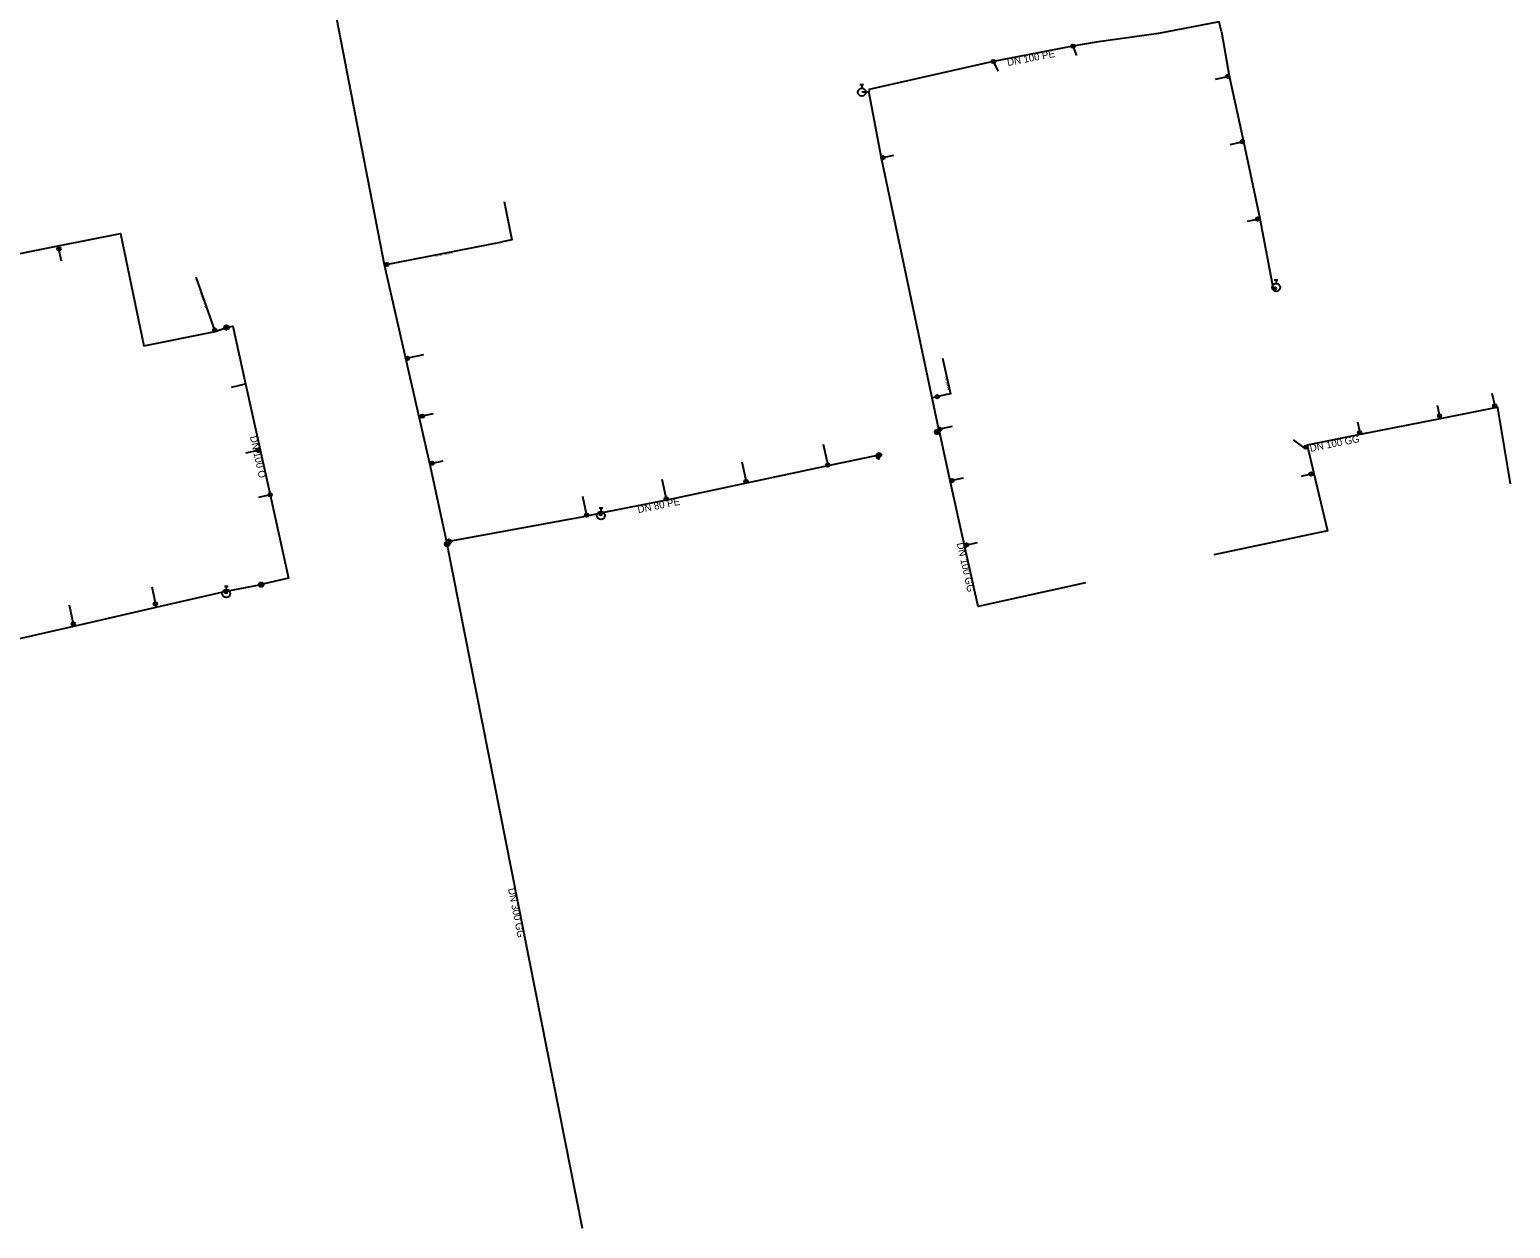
# Model space of a CAD drawing. Extents: x -452548 to -451108, y -1100145 to -1099658.
# Drawn here: x -452071.3 to -451742.6, y -1100145 to -1099878.8 of the extents above; entities that cross this region are included whole.
import ezdxf

# ---------------------------------------------------------------- set-up
doc = ezdxf.new("R2010")
doc.units = 0
for name, color, linetype in [('_hydrantova_odbocka_', 7, 'Continuous'), ('_kalosvod_', 7, 'Continuous'), ('_pripojka_prevzato_z_dokumentace_', 7, 'Continuous'), ('_pripojka_priblizne_', 7, 'Continuous'), ('_voda_smvak_prevzato_z_dokumentace_', 7, 'Continuous'), ('Default', 7, 'Continuous'), ('MoLevel 27', 7, 'Continuous'), ('MoLevel 28', 7, 'Continuous'), ('MoLevel 32', 7, 'Continuous'), ('MoLevel 46', 7, 'Continuous'), ('MoLevel 53', 7, 'Continuous'), ('MoLevel 55', 7, 'Continuous')]:
    doc.layers.add(name, color=color, linetype=linetype)

# ---------------------------------------------------------------- blocks, each defined once
blk = doc.blocks.new('_uzaver_')
at = {"layer": 'Default'}
for p, q in [((-0.000035, -0.000035), (0.000035, 0.000035)), ((0.000035, -0.000035), (-0.000035, 0.000035))]:
    blk.add_line(p, q, dxfattribs=at)
for radius in [0.00005, 0.0000025]:
    blk.add_circle((0, 0), radius, dxfattribs=at)
blk = doc.blocks.new('_uzaver_pripojka_')
at = {"layer": 'Default'}
for p, q in [((-0.000035, -0.000035), (0.000035, 0.000035)), ((0.000035, -0.000035), (-0.000035, 0.000035))]:
    blk.add_line(p, q, dxfattribs=at)
for radius in [0.00005, 0.0000025]:
    blk.add_circle((0, 0), radius, dxfattribs=at)
blk = doc.blocks.new('_hydrant_voda_')
at = {"layer": 'Default'}
for p, q in [((-0.000023, 0.000095), (0.000023, 0.000095)), ((0, 0.000095), (0, 0.00005))]:
    blk.add_line(p, q, dxfattribs=at)
blk.add_circle((0, 0), 0.00005, dxfattribs=at)

msp = doc.modelspace()

# ---------------------------------------------------------------- linework, layer by layer
at = {"layer": '_hydrantova_odbocka_'}
msp.add_line((-452027.74, -1100003.53), (-452027.69, -1100004.05), dxfattribs=at)
for points in [[(-451884.96, -1099892.67), (-451885.75, -1099892.66), (-451886.6, -1099892.67)], [(-451795.27, -1099936.33), (-451794.87, -1099936.26), (-451794.62, -1099936.05)], [(-451944.62, -1099986.22), (-451944.58, -1099986.45), (-451944.52, -1099986.71)]]:
    msp.add_lwpolyline(points, dxfattribs=at)
at = {"layer": '_kalosvod_'}
msp.add_lwpolyline([(-451883.09, -1099973.35), (-451882.99, -1099973.78), (-451882.87, -1099974.37)], dxfattribs=at)
at = {"layer": '_pripojka_prevzato_z_dokumentace_'}
for p, q in [((-451839.74, -1099882.46), (-451838.96, -1099884.55)), ((-451857.41, -1099885.86), (-451856.35, -1099887.97)), ((-451992.55, -1099931.06), (-451966.41, -1099925.9))]:
    msp.add_line(p, q, dxfattribs=at)
for points in [[(-451808.08, -1099889.76), (-451805.36, -1099889.16), (-451805.03, -1099889.08)], [(-451804.81, -1099904.28), (-451802.13, -1099903.68), (-451801.89, -1099903.63)], [(-451879.58, -1099906.73), (-451881.93, -1099907.23), (-451882.24, -1099907.3)], [(-451965.98, -1099916.92), (-451964.31, -1099925.49), (-451966.41, -1099925.9)], [(-451800.97, -1099921.36), (-451798.74, -1099920.87), (-451798.21, -1099920.74)], [(-452064.27, -1099930.21), (-452064.84, -1099927.48), (-452064.98, -1099926.81)], [(-452030.12, -1099945.84), (-452030.24, -1099945.51), (-452034.34, -1099933.8)], [(-451983.92, -1099951.02), (-451987.49, -1099951.78), (-451987.8, -1099951.84)], [(-451746.76, -1099959.56), (-451746.08, -1099962.34), (-451745.98, -1099962.79)], [(-451758.85, -1099962.22), (-451758.35, -1099964.56), (-451758.21, -1099965.21)], [(-451981.78, -1099964.13), (-451984.17, -1099964.64), (-451984.85, -1099964.79)], [(-451776.55, -1099965.9), (-451776.07, -1099968.27), (-451775.98, -1099968.74)], [(-451866.54, -1099966.95), (-451869.31, -1099967.55), (-451869.49, -1099967.59)], [(-452023.33, -1099972.8), (-452020.64, -1099972.21), (-452020.16, -1099972.1)], [(-451895.18, -1099970.88), (-451894.18, -1099975.5), (-451894.14, -1099975.7)], [(-451982.47, -1099975.18), (-451982, -1099975.08), (-451979.56, -1099974.54)], [(-451913.23, -1099974.79), (-451912.28, -1099979.15), (-451912.2, -1099979.53)], [(-451930.96, -1099978.63), (-451930.02, -1099982.98), (-451929.95, -1099983.3)], [(-451864.07, -1099978.39), (-451866.61, -1099978.94), (-451866.96, -1099979.02)], [(-451789.02, -1099977.95), (-451786.83, -1099977.48), (-451786.25, -1099977.36)], [(-452020.45, -1099982.6), (-452018.51, -1099982.2), (-452017.95, -1099982.09)], [(-451948.6, -1099982.44), (-451947.69, -1099986.61), (-451947.65, -1099986.83)], [(-451860.98, -1099992.75), (-451863.35, -1099993.26), (-451863.78, -1099993.35)], [(-452044.22, -1100002.54), (-452043.41, -1100006.34), (-452043.24, -1100007.07)], [(-452062.57, -1100006.51), (-452061.65, -1100010.76), (-452061.54, -1100011.25)]]:
    msp.add_lwpolyline(points, dxfattribs=at)
at = {"layer": '_pripojka_priblizne_'}
msp.add_line((-452026.56, -1099958.17), (-452023.39, -1099957.48), dxfattribs=at)
for points in [[(-451868.68, -1099951.73), (-451866.91, -1099959.67), (-451868.11, -1099959.93)], [(-451868.11, -1099959.93), (-451869.87, -1099960.31), (-451870.97, -1099960.54)], [(-451787.64, -1099971.45), (-451788.03, -1099971.53), (-451788.5, -1099971.61), (-451790.76, -1099969.87)]]:
    msp.add_lwpolyline(points, dxfattribs=at)
at = {"layer": '_voda_smvak_prevzato_z_dokumentace_'}
for p, q in [((-451869.38, -1099968.07), (-451869.86, -1099968.17)), ((-451978.26, -1099992.49), (-451978.75, -1099992.6)), ((-451978.66, -1099993.07), (-451978.75, -1099992.6)), ((-451948.57, -1100145.05), (-451978.66, -1099993.07))]:
    msp.add_line(p, q, dxfattribs=at)
for points in [[(-451978.75, -1099992.6), (-451982.47, -1099975.18), (-451984.85, -1099964.79), (-451987.8, -1099951.84), (-451992.55, -1099931.06), (-452003.12, -1099876.35)], [(-451806.74, -1099879.29), (-451807.26, -1099877.03), (-451820.76, -1099879.61), (-451834.59, -1099881.54), (-451839.74, -1099882.46), (-451857.41, -1099885.86), (-451884.96, -1099892.07), (-451884.96, -1099892.47)], [(-451806.74, -1099879.29), (-451805.03, -1099889.08), (-451801.89, -1099903.63), (-451798.21, -1099920.74), (-451795.27, -1099936.33)], [(-451869.38, -1099968.07), (-451869.49, -1099967.59), (-451882.24, -1099907.3), (-451884.93, -1099893.27), (-451884.96, -1099892.67), (-451884.96, -1099892.47)], [(-452346.93, -1099987.86), (-452316.58, -1099981.03), (-452302.11, -1099977.8), (-452284.59, -1099973.89), (-452266.73, -1099969.9), (-452234.9, -1099962.8), (-452147.49, -1099943.29), (-452132.25, -1099940.24), (-452115.2, -1099936.84), (-452096.89, -1099933.18), (-452079.42, -1099929.69), (-452064.98, -1099926.81), (-452051.17, -1099924.05), (-452046.02, -1099949.05), (-452030.12, -1099945.84), (-452027.65, -1099944.96)], [(-452027.65, -1099944.96), (-452026.22, -1099944.64), (-452023.39, -1099957.48), (-452020.16, -1099972.1), (-452017.95, -1099982.09), (-452013.86, -1100000.61), (-452019.95, -1100002.05)], [(-451742.62, -1099979.65), (-451745.44, -1099962.68), (-451745.98, -1099962.79), (-451758.21, -1099965.21), (-451775.98, -1099968.74), (-451787.73, -1099971.07), (-451786.25, -1099977.36), (-451783.25, -1099990.13), (-451808.47, -1099995.45)], [(-451836.92, -1100001.68), (-451860.78, -1100006.9), (-451863.78, -1099993.35), (-451866.96, -1099979.02), (-451869.38, -1099968.07)], [(-451882.79, -1099973.28), (-451894.14, -1099975.7), (-451912.2, -1099979.53), (-451928.83, -1099983.07), (-451929.95, -1099983.3), (-451944.62, -1099986.22), (-451947.65, -1099986.83), (-451948.37, -1099986.97), (-451978.26, -1099992.49)], [(-452234.84, -1100048.55), (-452220.84, -1100045.6), (-452206.09, -1100042.49), (-452191.46, -1100039.41), (-452173.67, -1100035.66), (-452156.49, -1100032.04), (-452145.92, -1100029.82), (-452078.82, -1100015.2), (-452061.54, -1100011.25), (-452043.24, -1100007.07), (-452027.74, -1100003.53), (-452019.95, -1100002.05)]]:
    msp.add_lwpolyline(points, dxfattribs=at)

# ---------------------------------------------------------------- block references
at = {"layer": 'MoLevel 27', "xscale": 5000, "yscale": 5000}
for p in [(-451794.87, -1099936.26), (-451944.58, -1099986.45), (-452027.72, -1100003.75)]:
    msp.add_blockref('_uzaver_', p, dxfattribs=at)
at = {"layer": 'MoLevel 27'}
for p, xscale, yscale, rotation in [((-452027.65, -1099944.96), 10000, 10000.000000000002, 12.545788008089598), ((-451869.86, -1099968.17), 10000, 9999.999999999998, 9.039482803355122), ((-451882.79, -1099973.28), 10000, 10000.000000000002, 9.884124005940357), ((-451882.99, -1099973.78), 5000, 5000.000000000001, -77.78428086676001), ((-451978.66, -1099993.07), 10000, 9999.999999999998, -78.80016861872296), ((-451978.26, -1099992.49), 10000, 9999.999999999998, 10.454404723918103), ((-452019.95, -1100002.05), 10000, 10000, 13.376097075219)]:
    msp.add_blockref('_uzaver_', p, dxfattribs=dict(at, xscale=xscale, yscale=yscale, rotation=rotation))
at = {"layer": 'MoLevel 28', "xscale": 17636.68430335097, "yscale": 17636.68430335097}
for p in [(-451886.6, -1099892.67), (-451794.62, -1099936.05), (-451944.52, -1099986.71), (-452027.69, -1100004.05)]:
    msp.add_blockref('_hydrant_voda_', p, dxfattribs=at)
at = {"layer": 'MoLevel 53', "xscale": 7999.999999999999, "yscale": 7999.999999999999}
for p in [(-451839.74, -1099882.46), (-451857.41, -1099885.86), (-451805.36, -1099889.16), (-451802.13, -1099903.68), (-451881.93, -1099907.23), (-451798.74, -1099920.87), (-452064.84, -1099927.48), (-451992.06, -1099930.95), (-452030.24, -1099945.51), (-451987.49, -1099951.78), (-451869.87, -1099960.31), (-451746.08, -1099962.34), (-451984.17, -1099964.64), (-451758.35, -1099964.56), (-451869.31, -1099967.55), (-451776.07, -1099968.27), (-452020.64, -1099972.21), (-451788.03, -1099971.53), (-451982, -1099975.08), (-451894.17, -1099975.5), (-451912.28, -1099979.15), (-451866.6, -1099978.94), (-451786.83, -1099977.48), (-452017.95, -1099982.09), (-451930.02, -1099982.98), (-451947.69, -1099986.61), (-451863.35, -1099993.26), (-452043.41, -1100006.34), (-452061.65, -1100010.76)]:
    msp.add_blockref('_uzaver_pripojka_', p, dxfattribs=at)

# ---------------------------------------------------------------- texts
at = {"layer": 'MoLevel 32'}
msp.add_text('DN 100 PE', height=0.455, rotation=282.5296, dxfattribs=at).set_placement((-451868.22, -1099955.89))
at = {"layer": 'MoLevel 46'}
for s, rotation, p in [('DN 100 PE', 10.8915, (-451854.18, -1099886.87)), ('DN 100 O', 282.4571, (-452022.45, -1099969.19)), ('DN 100 GG', 11.2208, (-451786.98, -1099972.56)), ('DN 80 PE', 11.2987, (-451936.22, -1099986.18)), ('DN 100 GG', 282.4952, (-451865.52, -1099992.89)), ('DN 300 GG', 281.1998, (-451965.14, -1100069.61))]:
    msp.add_text(s, height=1.605, rotation=rotation, dxfattribs=at).set_placement(p)
at = {"layer": 'MoLevel 55'}
for s, rotation, p in [('DN 40 - 6/4 PE', 11.1511, (-451981.46, -1099929.33)), ("DN 25 - 1'' O", 289.2879, (-452033.62, -1099937.23))]:
    msp.add_text(s, height=0.455, rotation=rotation, dxfattribs=at).set_placement(p)

doc.saveas('drawing.dxf')
